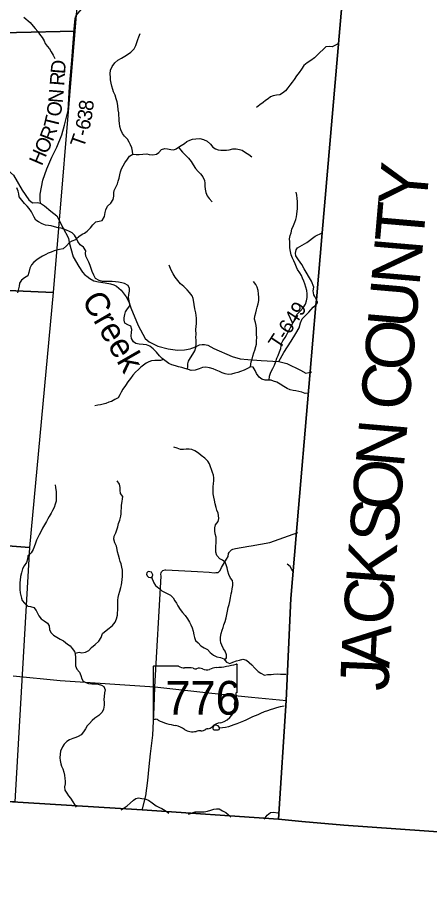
# Model space of a CAD drawing. Extents: x 1578669 to 1989827, y 208020 to 553079.
# Drawn here: x 1875771 to 1884281, y 343917 to 362037 of the extents above; entities that cross this region are included whole.
import ezdxf

# ---------------------------------------------------------------- set-up
doc = ezdxf.new("R2010")
doc.units = 0
for name, color, linetype in [('GM_X_Adjacent_County', 7, 'Continuous'), ('GM_X_Adjacent_County_Text', 7, 'Continuous'), ('GM_X_County', 7, 'Continuous'), ('GM_X_County_Road', 7, 'Continuous'), ('GM_X_Minor_Lake', 7, 'Continuous'), ('GM_X_Minor_River', 7, 'Continuous'), ('GM_X_Minor_River_Text', 7, 'Continuous'), ('GM_X_Section', 7, 'Continuous'), ('GM_X_State_Location', 7, 'Continuous'), ('GM_X_State_Route', 7, 'Continuous'), ('GM_X_State_Shield', 7, 'Continuous'), ('GM_X_Township', 7, 'Continuous'), ('GM_X_Township_Road', 7, 'Continuous'), ('GM_X_Township_Road_Text', 7, 'Continuous')]:
    doc.layers.add(name, color=color, linetype=linetype)

msp = doc.modelspace()

# ---------------------------------------------------------------- linework, layer by layer
at = {"layer": 'GM_X_Adjacent_County'}
for points in [[(1894919, 323647), (1895188, 327845), (1895523, 333111), (1895663, 335244), (1895699, 335683), (1895744, 336194), (1895779, 336659), (1896008, 339458), (1896189, 341713), (1896407, 344385), (1895952, 344420), (1891886, 344709), (1882510, 345364), (1881644, 345443), (1881166, 345493), (1881322, 347941), (1881415, 350049), (1881526, 351343), (1881811, 354649), (1881936, 356109), (1881945, 356213), (1882063, 357591), (1882647, 364366)], [(1860040, 346806), (1865771, 346465), (1867333, 346362), (1870033, 346179), (1871549, 346086), (1874430, 345924), (1878346, 345682), (1881166, 345493), (1881644, 345443), (1882510, 345364), (1891886, 344709), (1895952, 344420), (1896407, 344385), (1896189, 341713), (1896008, 339458), (1895779, 336659), (1895744, 336194), (1895699, 335683), (1895663, 335244), (1895523, 333111), (1895188, 327845), (1894919, 323647)]]:
    msp.add_lwpolyline(points, dxfattribs=at)
at = {"layer": 'GM_X_County'}
msp.add_lwpolyline([(1882647, 364366), (1882063, 357591), (1881945, 356213), (1881936, 356109), (1881811, 354649), (1881526, 351343), (1881415, 350049), (1881322, 347941), (1881166, 345493), (1878346, 345682), (1874430, 345924), (1871549, 346086), (1870033, 346179), (1867333, 346362), (1865771, 346465), (1860040, 346806)], dxfattribs=at)
at = {"layer": 'GM_X_County_Road'}
for points in [[(1880601, 351135), (1880982, 351203), (1881564, 351407)], [(1878606, 348222), (1878740, 350509), (1878734, 350549), (1878736, 350577), (1878744, 350599), (1878756, 350611), (1878776, 350625), (1878819, 350637), (1878837, 350635), (1879490, 350603), (1879729, 350590), (1879833, 350574), (1879871, 350580), (1879916, 350582), (1879960, 350624), (1879988, 350684), (1880091, 350858), (1880123, 350913), (1880133, 350973), (1880141, 350995), (1880149, 351011), (1880190, 351049), (1880220, 351067), (1880274, 351077), (1880550, 351126), (1880601, 351135)], [(1875683, 348451), (1876653, 348356), (1878606, 348222)]]:
    msp.add_lwpolyline(points, dxfattribs=at)
at = {"layer": 'GM_X_Minor_Lake'}
for points in [[(1878526, 350481), (1878556, 350497), (1878566, 350533), (1878541, 350589), (1878507, 350599), (1878471, 350601), (1878445, 350577), (1878437, 350547), (1878450, 350515), (1878480, 350487)], [(1878480, 350487), (1878518, 350479), (1878526, 350481)], [(1879938, 347392), (1879914, 347417), (1879886, 347426), (1879860, 347432), (1879834, 347422), (1879818, 347408), (1879804, 347390), (1879804, 347364), (1879812, 347346), (1879836, 347334), (1879866, 347332), (1879890, 347333), (1879914, 347335)], [(1879914, 347335), (1879934, 347344), (1879942, 347364), (1879942, 347387), (1879938, 347392)]]:
    msp.add_lwpolyline(points, dxfattribs=at)
at = {"layer": 'GM_X_Minor_River'}
for points in [[(1875901, 362045), (1876033, 361934), (1876092, 361862), (1876138, 361809), (1876187, 361749), (1876225, 361697), (1876281, 361624), (1876320, 361554), (1876344, 361502), (1876383, 361448), (1876429, 361391), (1876465, 361333), (1876510, 361259), (1876544, 361190)], [(1878153, 359217), (1878145, 359277), (1878130, 359349), (1878104, 359409), (1878080, 359467), (1878041, 359530), (1877981, 359588), (1877937, 359644), (1877904, 359721), (1877882, 359791), (1877879, 359857), (1877873, 359907), (1877869, 359957), (1877866, 360023), (1877864, 360073), (1877853, 360134), (1877841, 360222), (1877826, 360298), (1877812, 360360), (1877786, 360436), (1877753, 360505), (1877737, 360555), (1877718, 360621), (1877704, 360685), (1877694, 360751), (1877691, 360801), (1877683, 360875), (1877694, 360949), (1877724, 361027), (1877779, 361103), (1877841, 361157), (1877921, 361200), (1877989, 361242), (1878042, 361274), (1878114, 361325), (1878180, 361395), (1878217, 361463), (1878257, 361587), (1878278, 361641), (1878304, 361709)], [(1882404, 361504), (1882339, 361467), (1882270, 361431), (1882210, 361438), (1882140, 361434), (1882084, 361379), (1882016, 361315), (1881903, 361203), (1881831, 361150), (1881755, 361102), (1881686, 361046), (1881636, 360975), (1881587, 360905), (1881537, 360835), (1881485, 360757), (1881448, 360705), (1881400, 360642), (1881358, 360590), (1881305, 360528), (1881243, 360474), (1881187, 360443), (1881121, 360435), (1881053, 360423), (1880999, 360402), (1880946, 360360), (1880896, 360326), (1880846, 360286), (1880778, 360235), (1880711, 360179)], [(1876988, 357480), (1877039, 357517), (1877103, 357563), (1877155, 357589), (1877211, 357628), (1877278, 357694), (1877326, 357762), (1877390, 357818), (1877458, 357837), (1877522, 357851), (1877571, 357933), (1877583, 358011), (1877592, 358069), (1877632, 358144), (1877701, 358208), (1877749, 358282), (1877761, 358354), (1877760, 358420), (1877766, 358470), (1877803, 358538), (1877833, 358606), (1877851, 358658), (1877872, 358722), (1877882, 358792), (1877897, 358854), (1877921, 358912), (1877951, 358980), (1877990, 359041), (1878044, 359111), (1878086, 359173), (1878153, 359217), (1878225, 359210), (1878285, 359208), (1878357, 359220), (1878439, 359223), (1878492, 359213), (1878568, 359204), (1878642, 359220), (1878693, 359250), (1878745, 359313), (1878815, 359335), (1878867, 359327), (1878935, 359316), (1878999, 359308), (1879049, 359326), (1879099, 359359), (1879151, 359399), (1879218, 359441), (1879270, 359481), (1879330, 359508), (1879386, 359528), (1879456, 359536), (1879534, 359539), (1879614, 359523), (1879692, 359486), (1879761, 359422), (1879809, 359365), (1879860, 359329), (1879916, 359305), (1879968, 359298), (1880020, 359298), (1880086, 359302), (1880144, 359309), (1880222, 359327), (1880290, 359331), (1880358, 359316), (1880414, 359300), (1880484, 359255), (1880551, 359209), (1880611, 359160)], [(1879099, 359359), (1879141, 359309), (1879180, 359259), (1879248, 359188), (1879302, 359134), (1879355, 359068), (1879403, 358997), (1879450, 358923), (1879506, 358860), (1879553, 358810), (1879597, 358750), (1879637, 358674), (1879642, 358621), (1879644, 358559), (1879649, 358493), (1879663, 358427), (1879687, 358359), (1879732, 358301), (1879792, 358234)], [(1876897, 357594), (1876843, 357622), (1876784, 357649), (1876730, 357669), (1876670, 357688), (1876612, 357700), (1876538, 357718), (1876464, 357735), (1876410, 357747), (1876346, 357754), (1876277, 357778), (1876207, 357818), (1876151, 357855), (1876112, 357919), (1876060, 358028), (1876011, 358094), (1875967, 358144), (1875917, 358197), (1875858, 358267), (1875802, 358337), (1875795, 358402), (1875785, 358454), (1875754, 358524)], [(1880971, 354553), (1880977, 354637), (1881005, 354717), (1881048, 354793), (1881080, 354865), (1881109, 354941), (1881131, 355007), (1881155, 355065), (1881184, 355136), (1881208, 355204), (1881216, 355260), (1881227, 355312), (1881255, 355366), (1881297, 355432), (1881328, 355484), (1881356, 355536), (1881390, 355596), (1881427, 355666), (1881461, 355730), (1881490, 355797), (1881514, 355851), (1881550, 355915), (1881613, 355979), (1881673, 356045), (1881720, 356118), (1881740, 356190), (1881752, 356262), (1881757, 356334), (1881747, 356403), (1881728, 356471), (1881704, 356539), (1881685, 356599), (1881661, 356655), (1881637, 356710), (1881600, 356770), (1881558, 356836), (1881534, 356886), (1881507, 356955), (1881477, 357013), (1881454, 357069), (1881424, 357143), (1881408, 357206), (1881399, 357282), (1881395, 357340), (1881394, 357406), (1881392, 357470), (1881407, 357542), (1881421, 357594), (1881441, 357668), (1881470, 357748), (1881500, 357816), (1881521, 357868), (1881535, 357922), (1881543, 357976), (1881550, 358040), (1881552, 358090), (1881554, 358162), (1881553, 358240), (1881547, 358304), (1881540, 358372), (1881526, 358436)], [(1881783, 354282), (1881712, 354276), (1881642, 354303), (1881586, 354317), (1881523, 354330), (1881465, 354342), (1881403, 354356), (1881345, 354379), (1881271, 354419), (1881200, 354472), (1881126, 354510), (1881062, 354534), (1881008, 354551), (1880938, 354555), (1880886, 354556), (1880818, 354574), (1880765, 354616), (1880705, 354687), (1880678, 354755), (1880642, 354823), (1880582, 354830), (1880520, 354794), (1880450, 354760), (1880376, 354729), (1880321, 354709), (1880263, 354695), (1880191, 354678), (1880125, 354670), (1880059, 354686), (1880002, 354707), (1879942, 354733), (1879878, 354762), (1879814, 354784), (1879734, 354806), (1879664, 354819), (1879592, 354811), (1879522, 354786), (1879442, 354756), (1879360, 354751), (1879304, 354771), (1879227, 354793), (1879167, 354812), (1879099, 354830), (1879033, 354847), (1878957, 354869), (1878897, 354899), (1878840, 354938), (1878762, 355002), (1878706, 355057), (1878641, 355129), (1878571, 355198), (1878504, 355254), (1878436, 355281), (1878366, 355289), (1878282, 355293), (1878218, 355310), (1878165, 355342), (1878123, 355411), (1878121, 355465), (1878126, 355535), (1878132, 355599), (1878113, 355667), (1878049, 355697), (1877987, 355730), (1877971, 355792), (1877972, 355842), (1877986, 355910), (1878002, 355962), (1878043, 356028), (1878091, 356087), (1878094, 356138), (1878074, 356188), (1878062, 356256), (1878073, 356322), (1878083, 356390), (1878083, 356442), (1878054, 356510), (1877982, 356551), (1877924, 356565), (1877860, 356573), (1877794, 356584), (1877725, 356588), (1877603, 356589), (1877527, 356591), (1877457, 356608), (1877385, 356652), (1877344, 356719), (1877314, 356793), (1877292, 356857), (1877271, 356917), (1877241, 356987), (1877218, 357042), (1877182, 357114), (1877176, 357174), (1877183, 357224), (1877135, 357296), (1877062, 357349), (1877014, 357415), (1876990, 357475), (1876949, 357548), (1876897, 357594)], [(1876999, 357454), (1876968, 357446), (1876896, 357424), (1876846, 357396), (1876784, 357327), (1876711, 357263), (1876641, 357251), (1876583, 357238), (1876531, 357220), (1876469, 357196), (1876407, 357171), (1876357, 357145), (1876289, 357113), (1876218, 357072), (1876168, 357038), (1876106, 356990), (1876057, 356930), (1876023, 356866), (1876001, 356778), (1875982, 356708), (1875912, 356663), (1875850, 356617), (1875815, 356553), (1875803, 356495), (1875782, 356409), (1875768, 356355)], [(1879280, 354778), (1879289, 354837), (1879289, 354893), (1879303, 354945), (1879344, 355015), (1879390, 355087), (1879435, 355159), (1879457, 355225), (1879464, 355309), (1879462, 355373), (1879458, 355439), (1879459, 355493), (1879455, 355597), (1879460, 355659), (1879466, 355721), (1879469, 355783), (1879467, 355833), (1879461, 355885), (1879454, 355945), (1879436, 356024), (1879423, 356112), (1879415, 356166), (1879401, 356236), (1879376, 356296), (1879326, 356363), (1879273, 356419), (1879207, 356485), (1879140, 356544), (1879082, 356610), (1879028, 356679), (1878987, 356747), (1878959, 356797), (1878930, 356860), (1878902, 356924)], [(1880586, 354829), (1880601, 354928), (1880617, 354986), (1880633, 355050), (1880656, 355120), (1880674, 355171), (1880695, 355245), (1880707, 355299), (1880711, 355369), (1880712, 355424), (1880710, 355500), (1880711, 355556), (1880707, 355616), (1880701, 355678), (1880686, 355744), (1880668, 355812), (1880673, 355874), (1880693, 355944), (1880709, 356002), (1880724, 356062), (1880742, 356130), (1880757, 356200), (1880759, 356256), (1880751, 356338), (1880740, 356406), (1880720, 356471), (1880691, 356525), (1880649, 356591)], [(1878787, 354982), (1878728, 354961), (1878676, 354961), (1878606, 354959), (1878540, 354952), (1878484, 354930), (1878428, 354904), (1878375, 354864), (1878317, 354821), (1878267, 354775), (1878207, 354717), (1878154, 354658), (1878108, 354588), (1878051, 354518), (1877999, 354440), (1877949, 354366), (1877912, 354303), (1877884, 354249), (1877851, 354185), (1877781, 354151), (1877709, 354115), (1877659, 354096), (1877595, 354072), (1877539, 354056), (1877487, 354045), (1877433, 354035), (1877371, 354023)], [(1880054, 348773), (1880087, 348822), (1880091, 348886), (1880058, 348956), (1880028, 349010), (1879989, 349081), (1879971, 349131), (1879961, 349185), (1879966, 349251), (1879976, 349323), (1879999, 349391), (1880017, 349445), (1880035, 349505), (1880058, 349569), (1880080, 349649), (1880094, 349717), (1880107, 349785), (1880123, 349859), (1880142, 349921), (1880154, 349987), (1880169, 350059), (1880185, 350139), (1880197, 350191), (1880206, 350247), (1880218, 350311), (1880220, 350361), (1880211, 350417), (1880173, 350469), (1880136, 350543), (1880116, 350608), (1880100, 350678), (1880083, 350744), (1880061, 350798), (1880006, 350836), (1879948, 350867), (1879890, 350933), (1879867, 350999), (1879865, 351072), (1879869, 351128), (1879874, 351192), (1879876, 351248), (1879873, 351312), (1879857, 351380), (1879847, 351444), (1879846, 351502), (1879860, 351568), (1879917, 351632), (1879933, 351696), (1879925, 351756), (1879916, 351808), (1879892, 351870), (1879874, 351922), (1879851, 352003), (1879837, 352073), (1879824, 352135), (1879816, 352209), (1879813, 352283), (1879815, 352359), (1879821, 352413), (1879826, 352483), (1879826, 352537), (1879819, 352592), (1879801, 352644), (1879779, 352710), (1879760, 352766), (1879738, 352824), (1879700, 352879), (1879643, 352945), (1879563, 352999), (1879510, 353046), (1879436, 353096), (1879372, 353123), (1879320, 353131), (1879256, 353131), (1879202, 353120), (1879140, 353120), (1879068, 353146), (1879003, 353173)], [(1876961, 348915), (1877047, 348936), (1877101, 348927), (1877175, 348937), (1877245, 348973), (1877302, 349032), (1877374, 349098), (1877450, 349162), (1877497, 349239), (1877529, 349325), (1877600, 349387), (1877664, 349433), (1877732, 349488), (1877787, 349556), (1877817, 349624), (1877834, 349702), (1877838, 349752), (1877842, 349808), (1877841, 349880), (1877843, 349944), (1877845, 350014), (1877850, 350068), (1877864, 350126), (1877887, 350196), (1877905, 350272), (1877917, 350330), (1877934, 350434), (1877937, 350508), (1877939, 350564), (1877939, 350628), (1877926, 350696), (1877912, 350761), (1877894, 350811), (1877879, 350863), (1877857, 350939), (1877838, 351009), (1877830, 351059), (1877814, 351124), (1877783, 351194), (1877759, 351270), (1877770, 351334), (1877802, 351400), (1877823, 351460), (1877841, 351526), (1877857, 351592), (1877882, 351664), (1877904, 351742), (1877911, 351794), (1877913, 351852), (1877917, 351916), (1877918, 351974), (1877932, 352048), (1877942, 352100), (1877945, 352150), (1877899, 352214), (1877888, 352282), (1877888, 352336), (1877876, 352407), (1877831, 352473)], [(1876549, 352392), (1876555, 352334), (1876566, 352250), (1876568, 352172), (1876569, 352116), (1876569, 352058), (1876548, 351990), (1876530, 351924), (1876490, 351860), (1876463, 351808), (1876425, 351740), (1876399, 351688), (1876368, 351633), (1876330, 351567), (1876290, 351499), (1876257, 351439), (1876219, 351363), (1876192, 351305), (1876164, 351247), (1876140, 351189), (1876113, 351109), (1876091, 351056), (1876052, 350990), (1875986, 350924), (1875978, 350860), (1875953, 350788), (1875905, 350720), (1875873, 350660), (1875852, 350574), (1875832, 350502), (1875823, 350426), (1875821, 350376), (1875816, 350296), (1875816, 350232), (1875825, 350160), (1875841, 350110), (1875855, 350054), (1875868, 350002), (1875918, 349947), (1875986, 349891), (1876040, 349881), (1876107, 349860), (1876159, 349798), (1876181, 349742), (1876208, 349687), (1876260, 349625), (1876320, 349583), (1876387, 349534), (1876423, 349480), (1876434, 349408), (1876456, 349346), (1876512, 349287), (1876583, 349245), (1876653, 349206), (1876721, 349170), (1876802, 349103), (1876856, 349067), (1876902, 349017), (1876951, 348950), (1876965, 348900), (1876969, 348838), (1876966, 348784), (1876966, 348720), (1876971, 348658), (1876995, 348590), (1877049, 348523), (1877078, 348459), (1877100, 348389), (1877125, 348339), (1877185, 348312), (1877237, 348292), (1877305, 348284), (1877383, 348283), (1877435, 348275), (1877503, 348254), (1877557, 348232), (1877580, 348164), (1877570, 348098), (1877561, 348026), (1877557, 347962), (1877558, 347900), (1877558, 347842), (1877548, 347764), (1877517, 347702), (1877449, 347634), (1877367, 347578), (1877314, 347531), (1877256, 347469), (1877212, 347417), (1877175, 347359), (1877135, 347294), (1877083, 347234), (1877026, 347198), (1876974, 347180), (1876914, 347157), (1876846, 347127), (1876792, 347093), (1876737, 347040), (1876697, 346984), (1876659, 346896), (1876650, 346830)], [(1881466, 350603), (1881441, 350647), (1881401, 350709), (1881341, 350755)], [(1878537, 350486), (1878587, 350366), (1878623, 350316), (1878687, 350260), (1878754, 350203), (1878806, 350175), (1878878, 350142), (1878934, 350112), (1878985, 350058), (1879021, 350001), (1879054, 349947), (1879082, 349897), (1879134, 349818), (1879179, 349758), (1879231, 349694), (1879282, 349623), (1879324, 349557), (1879350, 349499), (1879377, 349441), (1879399, 349370), (1879414, 349294), (1879424, 349244), (1879449, 349178), (1879503, 349132), (1879557, 349071), (1879624, 349027), (1879694, 348992), (1879752, 348932), (1879823, 348879), (1879889, 348839), (1879963, 348831), (1880033, 348800), (1880088, 348730), (1880160, 348705), (1880216, 348731), (1880298, 348757), (1880354, 348772), (1880429, 348794), (1880500, 348773), (1880556, 348727), (1880612, 348675), (1880673, 348610), (1880745, 348542), (1880797, 348503), (1880870, 348465), (1880938, 348476), (1881010, 348478), (1881062, 348484), (1881132, 348491), (1881204, 348487), (1881323, 348483)], [(1881282, 347823), (1881194, 347810), (1881118, 347787), (1881056, 347769), (1880990, 347751), (1880932, 347728), (1880864, 347704), (1880793, 347672), (1880735, 347647), (1880679, 347621), (1880625, 347601), (1880555, 347572), (1880487, 347538), (1880437, 347512), (1880370, 347487), (1880300, 347461), (1880242, 347437), (1880186, 347416), (1880132, 347396), (1880068, 347384), (1879942, 347371)], [(1876650, 346830), (1876644, 346760), (1876649, 346702), (1876663, 346636), (1876679, 346586), (1876704, 346529), (1876726, 346463), (1876741, 346401), (1876749, 346331), (1876755, 346277), (1876752, 346219), (1876744, 346161), (1876748, 346089), (1876789, 346028), (1876827, 345974), (1876864, 345924), (1876912, 345849), (1876950, 345795), (1876980, 345741)], [(1877911, 345681), (1877976, 345722), (1878037, 345763), (1878101, 345818), (1878168, 345884), (1878218, 345920), (1878268, 345930), (1878342, 345921), (1878404, 345911), (1878475, 345884), (1878553, 345828), (1878633, 345763), (1878702, 345731), (1878754, 345709), (1878824, 345668), (1878899, 345618)], [(1879304, 345593), (1879441, 345640), (1879507, 345642), (1879563, 345640), (1879629, 345641), (1879699, 345653), (1879767, 345677), (1879830, 345696), (1879882, 345702), (1879936, 345704), (1880003, 345665), (1880077, 345627), (1880176, 345537)], [(1880867, 345493), (1880929, 345576), (1880997, 345628), (1881061, 345638), (1881148, 345623)]]:
    msp.add_lwpolyline(points, dxfattribs=at)
at = {"layer": 'GM_X_Section'}
for points in [[(1872183, 367145), (1877370, 366723), (1876954, 361754), (1874540, 361704), (1871754, 361853)], [(1871754, 361853), (1874540, 361704), (1876954, 361754), (1876506, 356359), (1871398, 356592)], [(1871398, 356592), (1876506, 356359), (1876016, 351102), (1871077, 351475)], [(1871077, 351475), (1876016, 351102), (1875714, 345849), (1870402, 346177), (1870200, 346190), (1870446, 348871)]]:
    msp.add_lwpolyline(points, close=True, dxfattribs=at)
at = {"layer": 'GM_X_State_Route'}
for points in [[(1878521, 346838), (1878564, 347226), (1878595, 347801), (1878606, 348222), (1879787, 348091), (1880607, 348008), (1881327, 347939)], [(1878348, 345679), (1878419, 345975), (1878466, 346289), (1878492, 346579), (1878521, 346838)]]:
    msp.add_lwpolyline(points, dxfattribs=at)
at = {"layer": 'GM_X_State_Shield'}
for p, q in [((1879099, 348648), (1878589, 348648)), ((1880312, 348121), (1880312, 348674)), ((1878572, 348630), (1878572, 347573)), ((1880312, 348122), (1880312, 348121))]:
    msp.add_line(p, q, dxfattribs=at)
for centre, major_axis, start_param, end_param in [((1878592, 348632), (20.2, 0), 1.712693, 3.28349), ((1879220, 348771), (196, 0), 4.042523, 4.731795), ((1879692, 350089), (1845, 0), 4.814394, 5.042369), ((1880293, 348676), (19.4, 0), 6.141152, 7.989035), ((1879285, 348055), (702, 0), 1.404758, 1.657858), ((1879444, 348637), (56.4, 0), 3.836095, 5.185415), ((1879527, 348515), (117, 0), 0.950623, 2.079405), ((1879679, 348683), (141, 0), 4.081561, 5.145723), ((1879928, 348325), (371, 0), 1.699011, 2.107814), ((1880308, 348081), (30, 0), 1.883978, 3.671073), ((1880292, 348119), (20.7, 0), 5.05454, 6.418171), ((1880382, 347890), (131, 0), 2.387724, 3.262537), ((1880117, 348011), (180, 0), 5.934695, 6.695948), ((1879796, 347820), (462, 0), 5.101752, 6.440018), ((1878592, 347571), (20.3, 0), 3.00124, 4.508301), ((1878595, 347679), (155, 0), 4.665946, 4.897461), ((1878627, 347512), (56, 0), 0.519207, 1.627899), ((1879334, 348462), (1333, 0), 4.195997, 4.488961), ((1878936, 347098), (417, 0), 0.823519, 1.323587), ((1879670, 347471), (149, 0), 4.937069, 5.64225), ((1879990, 347276), (253, 0), 1.647645, 2.488434), ((1879387, 347507), (265, 0), 4.026481, 4.996735), ((1879540, 347142), (217, 0), 1.495662, 1.94098), ((1879560, 347428), (141, 0), 4.691044, 5.507374), ((1879687, 347325), (39.7, 0), 1.147584, 2.315152)]:
    msp.add_ellipse(centre, major_axis=major_axis, ratio=0.8, start_param=start_param, end_param=end_param, dxfattribs=at)
at = {"layer": 'GM_X_Township'}
msp.add_lwpolyline([(1882647, 364366), (1882063, 357591), (1881945, 356213), (1881936, 356109), (1881811, 354649), (1881526, 351343), (1881415, 350049), (1881322, 347941), (1881166, 345493), (1878346, 345682), (1874430, 345924), (1871549, 346086), (1870033, 346179), (1867333, 346362), (1865771, 346465), (1860040, 346806), (1860651, 356303), (1860706, 357161), (1860710, 357224), (1861046, 362151)], dxfattribs=at)
at = {"layer": 'GM_X_Township_Road'}
for points in [[(1876246, 358209), (1876238, 358278), (1876240, 358390), (1876297, 358679), (1876376, 358914), (1876483, 359155), (1876582, 359361), (1876688, 359620), (1876741, 359815), (1876814, 360122), (1876847, 360612), (1876890, 361154), (1876949, 361881), (1876959, 362019), (1876974, 362063), (1877014, 362119), (1877143, 362264), (1877322, 362440), (1877376, 362546), (1877365, 362932)], [(1874454, 361439), (1874459, 361438), (1874507, 361418), (1874549, 361379), (1874884, 360651), (1874932, 360527), (1874978, 360448), (1875373, 360021), (1875421, 359933), (1875402, 359591), (1875332, 359423), (1875299, 359292), (1875285, 359190), (1875299, 359110), (1875323, 359057), (1875412, 358985), (1875574, 358886), (1875685, 358787), (1875865, 358473), (1876003, 358272), (1876083, 358210), (1876180, 358220), (1876246, 358209)], [(1876246, 358209), (1876331, 358149), (1876457, 358042), (1876581, 357945), (1876704, 357702), (1876822, 357485), (1876838, 357394), (1876918, 357095), (1877036, 356900), (1877116, 356783), (1877162, 356729), (1877202, 356698), (1877263, 356652), (1877349, 356606), (1877443, 356581), (1877584, 356559), (1877692, 356538), (1877761, 356522), (1877817, 356490), (1877913, 356413), (1878018, 356270), (1878054, 356200), (1878074, 356146), (1878114, 356045), (1878266, 355683), (1878406, 355416), (1878492, 355347), (1878667, 355252), (1878882, 355200), (1879075, 355173), (1879221, 355177), (1879335, 355202)], [(1881945, 356213), (1881926, 356250), (1881911, 356282), (1881896, 356314), (1881882, 356400), (1881894, 356473), (1881846, 356593), (1881696, 356853), (1881648, 356937), (1881579, 357034), (1881523, 357122), (1881511, 357171), (1881525, 357241), (1881556, 357287), (1881745, 357391), (1881922, 357523), (1882063, 357591)], [(1881168, 354940), (1881275, 355125), (1881422, 355361), (1881521, 355514), (1881589, 355632), (1881616, 355734), (1881650, 355817), (1881791, 355959), (1881881, 356059), (1881921, 356097), (1881936, 356109)], [(1881936, 356109), (1881948, 356119), (1881966, 356147), (1881966, 356171), (1881958, 356186), (1881945, 356213)], [(1879335, 355202), (1879370, 355210), (1879468, 355251), (1879477, 355254), (1879533, 355280), (1879583, 355290), (1879636, 355290), (1879706, 355276), (1879830, 355207), (1880206, 355043), (1880369, 354993), (1880531, 354976), (1880803, 354959), (1881168, 354940), (1881333, 354894), (1881614, 354760), (1881730, 354698), (1881851, 354728)]]:
    msp.add_lwpolyline(points, dxfattribs=at)

# ---------------------------------------------------------------- texts
at = {"layer": 'GM_X_Adjacent_County_Text'}
for s, rotation, p in [('Y', 85.0764, (1884214, 358108)), ('T', 85.0749, (1884149, 357362)), ('N', 85.0758, (1884074, 356481)), ('U', 85.0758, (1883998, 355600)), ('O', 85.0768, (1883922, 354719)), ('C', 85.0763, (1883852, 353908)), ('N', 85.0811, (1883750, 352724)), ('O', 85.1161, (1883675, 351843)), ('S', 85.2714, (1883619, 351169)), ('K', 85.655, (1883552, 350288)), ('C', 86.0603, (1883496, 349478)), ('A', 87.0714, (1883451, 348600)), ('J', 87.5181, (1883431, 348127))]:
    msp.add_text(s, height=1000, rotation=rotation, dxfattribs=at).set_placement(p)
at = {"layer": 'GM_X_Minor_River_Text'}
msp.add_text('Creek', height=500, rotation=299.8895, dxfattribs=at).set_placement((1877085, 356212))
at = {"layer": 'GM_X_State_Location'}
msp.add_text('776', height=1, rotation=0, dxfattribs=at).set_placement((1879070, 347958))
for s in ['s', 'r']:
    msp.add_text(s, height=1, dxfattribs=at).set_placement((1879423, 348031))
at = {"layer": 'GM_X_State_Shield'}
msp.add_text('776', height=696.1, dxfattribs=at).set_placement((1878827, 347648))
at = {"layer": 'GM_X_Township_Road_Text'}
for s, rotation, p in [('D', 85.565, (1876752, 360865)), ('R', 85.5618, (1876733, 360620)), ('N', 85.4187, (1876704, 360264)), ('O', 80.4653, (1876657, 359975)), ('8', 84.7751, (1877330, 360103)), ('3', 79.7101, (1877293, 359892)), ('T', 76.1174, (1876598, 359733)), ('6', 76.8566, (1877248, 359696)), ('R', 68.9959, (1876498, 359464)), ('-', 75.4934, (1877215, 359569)), ('O', 64.8687, (1876376, 359203)), ('T', 70.6394, (1877133, 359331)), ('H', 66.6182, (1876272, 358963)), ('T-649', 56.5258, (1881181, 355167))]:
    msp.add_text(s, height=300, rotation=rotation, dxfattribs=at).set_placement(p)

doc.saveas('drawing.dxf')
